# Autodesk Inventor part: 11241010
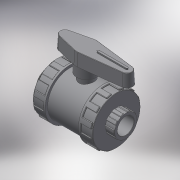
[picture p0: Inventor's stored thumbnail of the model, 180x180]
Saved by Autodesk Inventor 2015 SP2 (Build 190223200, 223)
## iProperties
Created: 2017-11
Part Number: 11241010
Material: Generic
Description: PLASSON BI STOP VALVE THR PVC 1"
Document SubType Name: Modeling
Designer: KIM
Density: 1 g/cm^3
Appearance: Default
Author: KIM
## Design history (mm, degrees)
derived "112410 - 112710.ipt"
feature "Solid1::112410 - 112710.ipt"
tag "TaggingFeature1"
body "Solid1"
other parameters: "d0" = 102, "d1" = 30.291, "d2" = 66, "d3" = 19, "d4" = 24.2328, "d5" = 13.3, "d7" = 42.4074, "d8" = 59.4, "d13" = 0.90873, "d23" = 19, "d24" = 63.36, "d25" = 0.60582, "d26" = 0.90873, "d27" = 9.9, "d28" = 4.95, "d29" = 14.25, "d30" = 0, "d35" = 0.90873, "d39" = 33, "d45" = 360 deg, "d47" = 0.60582, "d50" = 36.3, "d51" = 19.8, "d53" = 0, "d55" = 6.0582, "d56" = 3.0291, "d57" = 13.3, "d58" = 0, "d59" = 0.90873, "d61" = 360 deg, "d63" = 26.4, "d64" = 66, "d66" = 78, "d68" = 13.2, "d69" = 23.4, "d70" = 16.5, "d71" = 3 deg, "d73" = 1.32, "d74" = 31.2, "d75" = 1.98, "d76" = 0, "d77" = 0.60582, "G_" = 30.291, "l_" = 19, "H_" = 102, "K_" = 66, "F_" = 66, "J_" = 78, "d67" = 26.4, "d72" = 6.6
